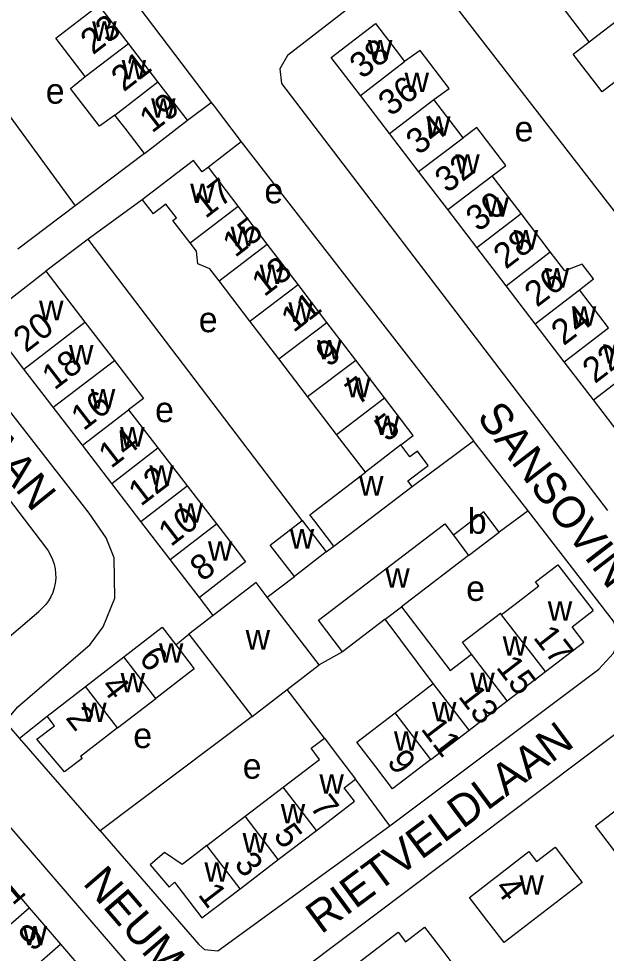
# Model space of a CAD drawing. Extents: x 158848 to 160613, y 385889 to 387762.
# Drawn here: x 160187.7 to 160280.6, y 386514.5 to 386662.2 of the extents above; entities that cross this region are included whole.
import ezdxf

# ---------------------------------------------------------------- set-up
doc = ezdxf.new("R2010")
doc.units = 0
for name, color, linetype in [('BLT_Basislijn', 7, 'Continuous'), ('BLT_Bebouwing', 7, 'Continuous'), ('BLT_Centroide', 7, 'Continuous'), ('BLT_Huisnummer', 7, 'Continuous'), ('BLT_Huisnummer_ tussenligend', 7, 'Continuous'), ('BLT_Onderverdeling_panden', 7, 'Continuous'), ('BLT_Straatnaam', 7, 'Continuous')]:
    doc.layers.add(name, color=color, linetype=linetype)

msp = doc.modelspace()

# ---------------------------------------------------------------- linework, layer by layer
at = {"layer": 'BLT_Basislijn'}
for p, q in [((160188.23, 386688.31), (160218.11, 386648.95)), ((160250.58, 386672.17), (160304.3, 386602.61)), ((160175.85, 386660.94), (160196.64, 386632.62)), ((160214.37, 386646.13), (160218.11, 386648.95)), ((160222.87, 386642.7), (160217.68, 386638.69)), ((160222.87, 386642.7), (160259.58, 386595.47)), ((160207.55, 386640.89), (160196.64, 386632.62)), ((160207.21, 386633.54), (160198.67, 386627.36)), ((160196.64, 386632.62), (160187.57, 386625.74)), ((160198.67, 386627.36), (160191.96, 386622.28)), ((160232.49, 386582.88), (160198.67, 386627.36)), ((160170.65, 386606.43), (160191.91, 386578.71)), ((160249.89, 386588.29), (160259.58, 386595.47)), ((160268.24, 386584.45), (160263.66, 386581.07)), ((160236.3, 386577.94), (160237.53, 386578.84)), ((160226.96, 386570.81), (160231.27, 386574.05)), ((160218.44, 386567.89), (160216.26, 386570.73)), ((160212.51, 386563.27), (160214.61, 386564.95)), ((160238.88, 386562.17), (160235.19, 386560.08)), ((160236.01, 386548.52), (160230.11, 386556.19)), ((160187.8, 386548.53), (160192.17, 386552.02)), ((160224.58, 386551.95), (160200.58, 386533.86)), ((160200.58, 386533.86), (160187.8, 386548.53)), ((160222.72, 386492.35), (160176.56, 386545.83)), ((160246.37, 386534.7), (160240.93, 386542.07))]:
    msp.add_line(p, q, dxfattribs=at)
for points in [[(160250.58, 386672.17), (160230.2, 386656.33), (160228.95, 386654.25), (160229.21, 386651.93), (160280.78, 386584.48)], [(160218.11, 386648.95), (160218.57, 386648.34), (160222.87, 386642.7)], [(160187.8, 386548.53), (160186.17, 386550.4), (160186.19, 386551.85), (160187.53, 386553.46), (160198.98, 386563.32), (160201.05, 386566.11), (160202.88, 386570.61), (160202.8, 386577), (160201.53, 386580.15), (160198.82, 386584.08), (160177.71, 386611.12)], [(160268.24, 386584.45), (160264.29, 386589.5), (160259.58, 386595.47)], [(160246.37, 386534.7), (160279.42, 386559.41), (160281.71, 386561.95), (160282.02, 386562.75), (160282.02, 386566.18), (160281.71, 386566.98), (160268.24, 386584.45)], [(160191.91, 386578.71), (160192.36, 386578.1), (160192.74, 386577.44), (160193.05, 386576.75), (160193.29, 386576.03), (160193.45, 386575.29), (160193.53, 386574.53), (160193.54, 386573.77), (160193.46, 386573.02), (160193.3, 386572.28), (160193.07, 386571.55), (160192.76, 386570.86), (160192.38, 386570.2), (160191.93, 386569.59), (160191.42, 386569.03), (160190.85, 386568.52)], [(160180.47, 386559.88), (160181.01, 386560.18), (160190.85, 386568.52)], [(160291.89, 386471.85), (160278.78, 386476.83), (160271.68, 386478.05), (160264.14, 386477.42), (160262.14, 386476.94), (160256.25, 386474.33), (160253.47, 386474.34), (160243.41, 386484.93), (160230, 386500.07), (160226.45, 386504.62), (160226.14, 386505.57), (160226.29, 386506.86), (160227.62, 386508.28), (160287.18, 386553.11)], [(160200.58, 386533.86), (160216.16, 386515.91), (160217.08, 386515.12), (160219.19, 386514.91), (160246.37, 386534.7)]]:
    msp.add_lwpolyline(points, dxfattribs=at)
at = {"layer": 'BLT_Bebouwing'}
for p, q in [((160205.04, 386658.26), (160200.38, 386664.32)), ((160277.88, 386658.52), (160273.28, 386664.49)), ((160209.7, 386652.19), (160205.04, 386658.26)), ((160214.37, 386646.13), (160209.7, 386652.19)), ((160246.31, 386644.02), (160241.7, 386650.03)), ((160257.95, 386643.32), (160253.3, 386649.39)), ((160207.55, 386640.89), (160214.37, 386646.13)), ((160250.91, 386638.02), (160246.31, 386644.02)), ((160222.37, 386632.55), (160217.68, 386638.69)), ((160255.52, 386632.01), (160250.91, 386638.02)), ((160267.12, 386631.37), (160262.54, 386637.34)), ((160226.97, 386626.54), (160222.37, 386632.55)), ((160260.12, 386626), (160255.52, 386632.01)), ((160271.73, 386625.36), (160267.12, 386631.37)), ((160231.85, 386620.16), (160226.97, 386626.54)), ((160264.73, 386619.99), (160260.12, 386626)), ((160183.21, 386615.47), (160191.96, 386622.28)), ((160224.24, 386614.4), (160219.39, 386620.74)), ((160236.41, 386614.19), (160231.85, 386620.16)), ((160269.33, 386613.99), (160264.73, 386619.99)), ((160280.94, 386613.34), (160276.33, 386619.35)), ((160228.8, 386608.43), (160224.24, 386614.4)), ((160240.98, 386608.23), (160236.41, 386614.19)), ((160273.94, 386607.98), (160269.33, 386613.99)), ((160233.37, 386602.47), (160228.8, 386608.43)), ((160245.54, 386602.26), (160240.98, 386608.23)), ((160278.55, 386601.97), (160273.94, 386607.98)), ((160193.13, 386600.8), (160188.51, 386606.82)), ((160237.93, 386596.5), (160233.37, 386602.47)), ((160283.15, 386595.97), (160278.55, 386601.97)), ((160197.76, 386594.79), (160193.13, 386600.8)), ((160205.06, 386600.4), (160209.68, 386594.39)), ((160242.49, 386590.53), (160237.93, 386596.5)), ((160202.39, 386588.77), (160197.76, 386594.79)), ((160209.68, 386594.39), (160214.31, 386588.38)), ((160207.01, 386582.76), (160202.39, 386588.77)), ((160214.31, 386588.38), (160218.94, 386582.36)), ((160237.53, 386578.84), (160249.89, 386588.29)), ((160211.64, 386576.75), (160207.01, 386582.76)), ((160232.49, 386582.88), (160236.3, 386577.94)), ((160258.81, 386577.37), (160263.66, 386581.07)), ((160216.26, 386570.73), (160211.64, 386576.75)), ((160236.3, 386577.94), (160231.27, 386574.05)), ((160258.81, 386577.37), (160248.18, 386569.27)), ((160269.39, 386573.2), (160272.94, 386575.92)), ((160272.94, 386575.92), (160278.5, 386568.67)), ((160269.91, 386572.51), (160269.39, 386573.2)), ((160235.19, 386560.08), (160226.96, 386570.81)), ((160218.44, 386567.89), (160214.61, 386564.95)), ((160264.02, 386568), (160263.83, 386568.25)), ((160275.17, 386566.11), (160278.5, 386568.67)), ((160245.63, 386567.32), (160238.88, 386562.17)), ((160214.61, 386564.95), (160224.58, 386551.95)), ((160198.23, 386556.7), (160204.3, 386561.38)), ((160230.11, 386556.19), (160235.19, 386560.08)), ((160264.93, 386554.43), (160270.97, 386559.07)), ((160192.17, 386552.02), (160198.23, 386556.7)), ((160224.58, 386551.95), (160230.11, 386556.19)), ((160247.19, 386552.54), (160253.23, 386557.17)), ((160203.3, 386550.13), (160209.37, 386554.81)), ((160258.89, 386549.8), (160264.93, 386554.43)), ((160252.84, 386545.16), (160258.89, 386549.8)), ((160194.93, 386543.2), (160190.56, 386548.34)), ((160223.49, 386536.18), (160229.52, 386540.79)), ((160217.45, 386531.57), (160223.49, 386536.18)), ((160228.71, 386529.34), (160234.75, 386533.95)), ((160222.68, 386524.73), (160228.71, 386529.34)), ((160184.43, 386527.48), (160189.37, 386521.73)), ((160189.37, 386521.73), (160194.31, 386515.98)), ((160194.31, 386515.98), (160199.26, 386510.23))]:
    msp.add_line(p, q, dxfattribs=at)
for points in [[(160198.22, 386653.02), (160193.56, 386659.08), (160196.97, 386661.7), (160200.38, 386664.32)], [(160241.7, 386650.03), (160237.1, 386656.04), (160244.09, 386661.4), (160247.37, 386657.13), (160248.7, 386655.4)], [(160282.48, 386652.54), (160279.95, 386650.59), (160275.35, 386656.57), (160277.88, 386658.52)], [(160253.3, 386649.39), (160255.76, 386651.14), (160251.17, 386657.13), (160248.7, 386655.4)], [(160202.89, 386646.95), (160200.48, 386645.18), (160195.88, 386651.16), (160198.22, 386653.02)], [(160207.55, 386640.89), (160204.5, 386644.85), (160202.89, 386646.95)], [(160262.54, 386637.34), (160264.69, 386638.97), (160260.12, 386644.97), (160257.95, 386643.32)], [(160217.68, 386638.69), (160216.71, 386637.95), (160215.34, 386639.75), (160207.21, 386633.54)], [(160207.21, 386633.54), (160208.92, 386631.32)], [(160214.79, 386626.76), (160212.08, 386630.3), (160212.61, 386630.7), (160210.95, 386632.87), (160208.92, 386631.32)], [(160219.39, 386620.74), (160217.92, 386622.66), (160216, 386623.42), (160215.79, 386625.45), (160214.79, 386626.76)], [(160276.33, 386619.35), (160278.54, 386621.09), (160276.75, 386623.41), (160274.04, 386622.35), (160271.73, 386625.36)], [(160191.96, 386622.28), (160198.15, 386614.23)], [(160188.51, 386606.82), (160183.89, 386612.83), (160184.74, 386613.49), (160183.21, 386615.47)], [(160198.15, 386614.23), (160202.82, 386608.17)], [(160202.82, 386608.17), (160207.43, 386602.18), (160205.06, 386600.4)], [(160248.09, 386594.84), (160250.06, 386596.35), (160245.54, 386602.26)], [(160249.89, 386588.29), (160249.22, 386589.16), (160252.43, 386591.61), (160250.71, 386593.86), (160249.52, 386592.95), (160248.09, 386594.84)], [(160237.53, 386578.84), (160234.49, 386582.82), (160233.72, 386583.82), (160242.49, 386590.53)], [(160263.66, 386581.07), (160261.23, 386584.26), (160256.42, 386580.59)], [(160231.27, 386574.05), (160227.46, 386578.99), (160232.49, 386582.88)], [(160218.94, 386582.36), (160220.52, 386580.31), (160223.56, 386576.35), (160216.26, 386570.73)], [(160238.88, 386562.17), (160235.09, 386567.15), (160255.05, 386582.38), (160256.42, 386580.59)], [(160226.96, 386570.81), (160225.22, 386573.09), (160218.44, 386567.89)], [(160269.91, 386572.51), (160266.16, 386569.64), (160264.02, 386568)], [(160248.18, 386569.27), (160255.89, 386559.21), (160259.27, 386561.81)], [(160259.27, 386561.81), (160257.85, 386563.66), (160263.83, 386568.25)], [(160253.23, 386557.17), (160245.63, 386567.32)], [(160204.3, 386561.38), (160210.36, 386566.05), (160212.51, 386563.27)], [(160270.97, 386559.07), (160277.01, 386563.7), (160275.17, 386566.11)], [(160212.51, 386563.27), (160213.04, 386562.58), (160215.43, 386559.48), (160209.37, 386554.81)], [(160190.56, 386548.34), (160193.35, 386550.49), (160192.17, 386552.02)], [(160252.84, 386545.16), (160246.8, 386540.53), (160244.15, 386543.98), (160241.14, 386547.9), (160247.19, 386552.54)], [(160203.3, 386550.13), (160201.43, 386548.68), (160197.47, 386545.63), (160197.7, 386545.33), (160194.93, 386543.2)], [(160229.52, 386540.79), (160235.24, 386545.16), (160233.9, 386546.92), (160236.01, 386548.52)], [(160236.01, 386548.52), (160237.9, 386546.04), (160240.93, 386542.07)], [(160234.75, 386533.95), (160240.79, 386538.56), (160239.15, 386540.7), (160240.93, 386542.07)], [(160288.31, 386541.89), (160289.36, 386540.51), (160292.33, 386542.78), (160296.65, 386537.11), (160292.67, 386534.08), (160284.22, 386527.64), (160281.55, 386531.15), (160278.86, 386534.69), (160288.31, 386541.89)], [(160217.45, 386531.57), (160215.73, 386530.26), (160213.54, 386528.58), (160210.75, 386530.44), (160208.47, 386528.49), (160211.45, 386525), (160212.34, 386525.76), (160216.64, 386520.12), (160222.68, 386524.73)], [(160268.35, 386530.61), (160269.54, 386529.06), (160272.47, 386531.32), (160275.52, 386527.36), (160276.76, 386525.74), (160264.41, 386516.23), (160261.67, 386519.79), (160258.93, 386523.35), (160268.35, 386530.61)], [(160247.67, 386517.9), (160248.86, 386516.36), (160251.83, 386518.66), (160254.89, 386514.7), (160256.17, 386513.04), (160247.63, 386506.58), (160243.65, 386503.56), (160238.21, 386510.59), (160247.67, 386517.9)]]:
    msp.add_lwpolyline(points, dxfattribs=at)
at = {"layer": 'BLT_Onderverdeling_panden'}
for p, q in [((160277.88, 386658.52), (160284.67, 386663.74)), ((160198.22, 386653.02), (160205.04, 386658.26)), ((160241.7, 386650.03), (160248.7, 386655.4)), ((160202.89, 386646.95), (160209.7, 386652.19)), ((160246.31, 386644.02), (160253.3, 386649.39)), ((160250.91, 386638.02), (160257.95, 386643.32)), ((160255.52, 386632.01), (160262.54, 386637.34)), ((160214.79, 386626.76), (160222.37, 386632.55)), ((160260.12, 386626), (160267.12, 386631.37)), ((160219.39, 386620.74), (160226.97, 386626.54)), ((160264.73, 386619.99), (160271.73, 386625.36)), ((160224.24, 386614.4), (160231.85, 386620.16)), ((160269.33, 386613.99), (160276.33, 386619.35)), ((160188.51, 386606.82), (160198.15, 386614.23)), ((160228.8, 386608.43), (160236.41, 386614.19)), ((160273.94, 386607.98), (160280.94, 386613.34)), ((160193.13, 386600.8), (160202.82, 386608.17)), ((160233.37, 386602.47), (160240.98, 386608.23)), ((160278.55, 386601.97), (160285.54, 386607.34)), ((160237.93, 386596.5), (160245.54, 386602.26)), ((160197.76, 386594.79), (160205.06, 386600.4)), ((160248.09, 386594.84), (160242.49, 386590.53)), ((160202.39, 386588.77), (160209.68, 386594.39)), ((160207.01, 386582.76), (160214.31, 386588.38)), ((160211.64, 386576.75), (160218.94, 386582.36)), ((160256.42, 386580.59), (160258.81, 386577.37)), ((160245.63, 386567.32), (160248.18, 386569.27)), ((160270.97, 386559.07), (160264.02, 386568)), ((160209.37, 386554.81), (160204.3, 386561.38)), ((160264.93, 386554.43), (160259.27, 386561.81)), ((160203.3, 386550.13), (160198.23, 386556.7)), ((160258.89, 386549.8), (160253.23, 386557.17)), ((160252.84, 386545.16), (160247.19, 386552.54)), ((160234.75, 386533.95), (160229.52, 386540.79)), ((160228.71, 386529.34), (160223.49, 386536.18)), ((160222.68, 386524.73), (160217.45, 386531.57)), ((160182.31, 386515.6), (160189.37, 386521.73)), ((160187.24, 386509.85), (160194.31, 386515.98))]:
    msp.add_line(p, q, dxfattribs=at)

# ---------------------------------------------------------------- texts
at = {"layer": 'BLT_Centroide'}
for s, p in [('w', (160199.3, 386658.66)), ('w', (160242.9, 386655.72)), ('w', (160203.97, 386652.59)), ('w', (160248.69, 386650.56)), ('e', (160191.97, 386648.74)), ('w', (160208.62, 386646.53)), ('w', (160252.1, 386643.69)), ('e', (160266.08, 386642.79)), ('w', (160256.71, 386637.69)), ('w', (160214.8, 386633.03)), ('e', (160226.53, 386633)), ('w', (160261.32, 386630.89)), ('w', (160221.2, 386626.22)), ('w', (160265.93, 386625.69)), ('w', (160225.77, 386620.25)), ('w', (160270.85, 386619.69)), ('w', (160190.91, 386614.53)), ('w', (160230.33, 386614.28)), ('w', (160275.13, 386613.66)), ('e', (160216.16, 386612.64)), ('w', (160234.88, 386608.34)), ('w', (160280.06, 386607.66)), ('w', (160195.64, 386607.53)), ('w', (160239.45, 386602.38)), ('w', (160199.09, 386600.59)), ('e', (160209.25, 386598.43)), ('w', (160244.02, 386596.41)), ('w', (160203.72, 386594.59)), ('w', (160208.34, 386588.56)), ('w', (160241.49, 386586.84)), ('w', (160212.97, 386582.56)), ('b', (160258.69, 386580.81)), ('w', (160230.54, 386578.47)), ('w', (160217.6, 386576.56)), ('w', (160245.64, 386572.28)), ('e', (160258.43, 386570.2)), ('w', (160271.33, 386567.06)), ('w', (160223.56, 386562.52)), ('w', (160209.86, 386560.44)), ('w', (160264.2, 386561.56)), ('w', (160203.8, 386555.75)), ('w', (160259.08, 386555.8)), ('w', (160197.73, 386551.08)), ('w', (160253.03, 386551.17)), ('e', (160205.8, 386546.96)), ('w', (160247, 386546.55)), ('e', (160223.1, 386542.12)), ('w', (160235.23, 386539.73)), ('w', (160229.12, 386535.06)), ('w', (160223.08, 386530.45)), ('w', (160217.05, 386525.84)), ('w', (160266.84, 386523.78)), ('w', (160188.31, 386515.78))]:
    msp.add_text(s, height=4, dxfattribs=at).set_placement(p)
at = {"layer": 'BLT_Huisnummer'}
for s, rotation, p in [('23', 37.5442, (160199.42, 386656.36)), ('38', 37.4703, (160241.96, 386652.53)), ('19', 37.5495, (160208.75, 386643.99)), ('34', 37.4703, (160250.88, 386640.51)), ('17', 37.578, (160217.21, 386630.49)), ('30', 37.4703, (160260.35, 386628.39)), ('13', 37.578, (160226.5, 386618.13)), ('26', 37.4703, (160269.61, 386616.48)), ('20', 37.564, (160188.83, 386609.3)), ('9', 37.578, (160236.63, 386607)), ('22', 37.4703, (160278.77, 386604.42)), ('16', 37.564, (160197.93, 386596.97)), ('5', 37.578, (160245.91, 386595.2)), ('12', 37.564, (160207, 386585.04)), ('8', 37.564, (160216.74, 386573.14)), ('17', 307.9571, (160268.91, 386564.4)), ('6', 307.6473, (160206.56, 386561.1)), ('13', 307.4863, (160257.05, 386555.09)), ('2', 307.6418, (160194.99, 386551.71)), ('9', 307.4937, (160245.77, 386544.8)), ('7', 307.3758, (160233.59, 386537.66)), ('1', 307.3758, (160215.91, 386523.78)), ('4', 307.613, (160262.81, 386524.79)), ('9', 40.6838, (160189.84, 386514.69))]:
    msp.add_text(s, height=4, rotation=rotation, dxfattribs=at).set_placement(p)
at = {"layer": 'BLT_Huisnummer_ tussenligend'}
for s, rotation, p in [('21', 37.5495, (160204.28, 386650.51)), ('36', 37.4703, (160246.49, 386646.62)), ('32', 37.4703, (160255.44, 386634.5)), ('15', 37.578, (160221.9, 386624.34)), ('28', 37.4703, (160264.69, 386622.48)), ('11', 37.578, (160231.14, 386612.49)), ('24', 37.4703, (160273.83, 386610.41)), ('18', 37.564, (160193.34, 386603.39)), ('7', 37.578, (160241.3, 386600.97)), ('14', 37.564, (160202.28, 386591.02)), ('10', 37.564, (160211.74, 386578.67)), ('15', 307.4863, (160263.04, 386559.69)), ('4', 307.6418, (160200.54, 386556.64)), ('11', 307.4937, (160251.15, 386549.97)), ('5', 307.3758, (160227.83, 386533.15)), ('3', 307.3758, (160221.63, 386528.64)), ('11', 40.6838, (160184.48, 386520.06))]:
    msp.add_text(s, height=4, rotation=rotation, dxfattribs=at).set_placement(p)
at = {"layer": 'BLT_Straatnaam'}
for s, rotation, p in [('NEUMANNLAAN', 308.7694, (160157.93, 386624.03)), ('SANSOVINOSTRAAT', 307.5823, (160259.98, 386599.2)), ('RIETVELDLAAN', 36.6263, (160235.51, 386517.47)), ('NEUMANNLAAN', 310.7694, (160197.69, 386525.55))]:
    msp.add_text(s, height=5, rotation=rotation, dxfattribs=at).set_placement(p)

doc.saveas('drawing.dxf')
